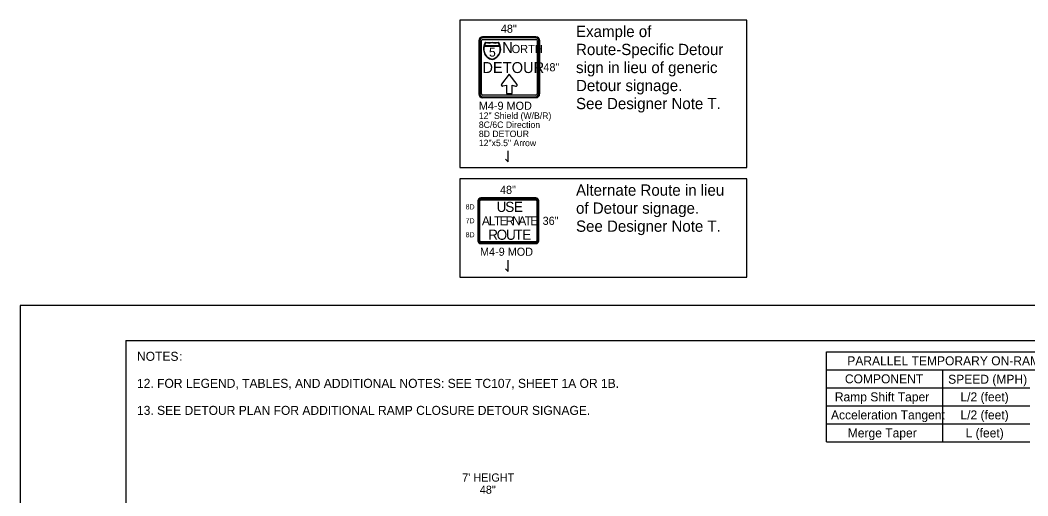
# Model space of a CAD drawing. Extents: x 99999 to 100116, y 99995 to 100013.
# Drawn here: x 100039.06 to 100048.01, y 100009 to 100013.22 of the extents above; entities that cross this region are included whole.
import ezdxf

# ---------------------------------------------------------------- set-up
doc = ezdxf.new("R2010")
doc.units = 0
for name, color, linetype in [('SH_GI_GeneralNotesBodyText', 7, 'Continuous'), ('SH_GI_PlotLimits', 7, 'Continuous'), ('SH_GI_SheetBorder', 7, 'Continuous'), ('SH_TI_Tables', 7, 'Continuous'), ('TR_SN_ConstructionSigns', 7, 'Continuous'), ('TR_WZ_WorkZoneDetails', 7, 'Continuous')]:
    doc.layers.add(name, color=color, linetype=linetype)

msp = doc.modelspace()

# ---------------------------------------------------------------- linework, layer by layer
at = {"layer": 'SH_GI_PlotLimits'}
msp.add_lwpolyline([(100039.0625, 99999.6875), (100056.0625, 99999.6875), (100056.0625, 100010.6875), (100039.0625, 100010.6875)], close=True, dxfattribs=at)
at = {"layer": 'SH_GI_SheetBorder'}
for q in [(100040, 100000), (100055.75, 100010.375)]:
    msp.add_line((100040, 100010.375), q, dxfattribs=at)
at = {"layer": 'SH_TI_Tables'}
for p, q in [((100046.2222, 100010.275), (100049.5278, 100010.275)), ((100046.2222, 100009.475), (100046.2222, 100010.275)), ((100046.2222, 100010.115), (100049.5278, 100010.115)), ((100047.2536, 100010.115), (100047.2536, 100009.795)), ((100046.2222, 100009.955), (100048.0278, 100009.955)), ((100046.2222, 100009.795), (100048.0278, 100009.795)), ((100047.2536, 100009.795), (100047.2536, 100009.635)), ((100046.2222, 100009.635), (100048.0278, 100009.635)), ((100047.2536, 100009.635), (100047.2536, 100009.475)), ((100046.2222, 100009.475), (100048.0278, 100009.475))]:
    msp.add_line(p, q, dxfattribs=at)
at = {"layer": 'TR_SN_ConstructionSigns'}
for p, q in [((100043.1354, 100013.0373), (100043.1354, 100012.5648)), ((100043.1438, 100013.0373), (100043.1438, 100012.5648)), ((100043.1579, 100012.5648), (100043.1579, 100013.0373)), ((100043.6416, 100013.0711), (100043.1691, 100013.0711)), ((100043.6416, 100013.0626), (100043.1691, 100013.0626)), ((100043.1691, 100013.0486), (100043.6416, 100013.0486)), ((100043.3228, 100012.9875), (100043.1823, 100012.9875)), ((100043.1823, 100012.9875), (100043.3228, 100012.9875)), ((100043.1834, 100012.9912), (100043.3217, 100012.9912)), ((100043.3217, 100012.9912), (100043.1834, 100012.9912)), ((100043.6529, 100013.0373), (100043.6529, 100012.5648)), ((100043.6669, 100012.5648), (100043.6669, 100013.0373)), ((100043.6754, 100012.5648), (100043.6754, 100013.0373)), ((100043.6416, 100012.5536), (100043.1691, 100012.5536)), ((100043.1691, 100012.5395), (100043.6416, 100012.5395)), ((100043.1691, 100012.5311), (100043.6416, 100012.5311)), ((100043.1277, 100011.6152), (100043.1277, 100011.2608)), ((100043.1347, 100011.6152), (100043.1347, 100011.2608)), ((100043.1446, 100011.2608), (100043.1446, 100011.6152)), ((100043.6424, 100011.6405), (100043.153, 100011.6405)), ((100043.6424, 100011.6335), (100043.153, 100011.6335)), ((100043.153, 100011.6236), (100043.6424, 100011.6236)), ((100043.6508, 100011.6152), (100043.6508, 100011.2608)), ((100043.6607, 100011.2608), (100043.6607, 100011.6152)), ((100043.6677, 100011.2608), (100043.6677, 100011.6152)), ((100043.6424, 100011.2524), (100043.153, 100011.2524)), ((100043.153, 100011.2425), (100043.6424, 100011.2425)), ((100043.153, 100011.2355), (100043.6424, 100011.2355))]:
    msp.add_line(p, q, dxfattribs=at)
msp.add_lwpolyline([(100043.3367, 100012.6494), (100043.3356, 100012.6478), (100043.335, 100012.6461), (100043.3347, 100012.6441), (100043.3348, 100012.6424), (100043.335, 100012.6412), (100043.3356, 100012.6398), (100043.3373, 100012.6375), (100043.3386, 100012.6364), (100043.34, 100012.6355), (100043.3417, 100012.6348), (100043.3432, 100012.6345), (100043.3447, 100012.6343), (100043.3465, 100012.6343), (100043.3478, 100012.6346), (100043.3795, 100012.6424), (100043.3795, 100012.5671), (100043.4307, 100012.5671), (100043.4307, 100012.6429), (100043.4617, 100012.6337), (100043.4647, 100012.6331), (100043.4681, 100012.6334), (100043.4703, 100012.6342), (100043.4733, 100012.6362), (100043.4752, 100012.6389), (100043.476, 100012.6414), (100043.4761, 100012.6436), (100043.4754, 100012.6463), (100043.4746, 100012.6477), (100043.4051, 100012.7405), (100043.3367, 100012.6494)], dxfattribs=at)
for centre, radius, start, end in [((100043.1691, 100013.0373), 0.0337, 90, 180), ((100043.1691, 100013.0373), 0.0253, 90, 180), ((100043.1691, 100013.0373), 0.0113, 90, 180), ((100043.2725, 100012.9642), 0.0973, 142.16169, 258.18105), ((100043.2715, 100012.9633), 0.0925, 164.85517, 258.18105), ((100043.2715, 100012.9633), 0.0925, 164.85517, 258.18105), ((100043.2715, 100012.9633), 0.0925, 142.16169, 162.48397), ((100043.2715, 100012.9633), 0.0925, 142.16169, 162.48397), ((100043.2245, 100013.1212), 0.1014, 253.48525, 286.04538), ((100043.2259, 100013.1124), 0.0964, 253.48525, 286.04538), ((100043.2259, 100013.1124), 0.0964, 253.48525, 286.04538), ((100043.2806, 100013.1212), 0.1014, 253.95462, 286.51475), ((100043.2792, 100013.1124), 0.0964, 253.95462, 286.51475), ((100043.2792, 100013.1124), 0.0964, 253.95462, 286.51475), ((100043.2325, 100012.9642), 0.0974, 281.90384, 37.84925), ((100043.2335, 100012.9633), 0.0925, 281.90384, 15.1558), ((100043.2335, 100012.9633), 0.0925, 281.90384, 15.1558), ((100043.2335, 100012.9633), 0.0925, 17.52691, 37.84925), ((100043.2335, 100012.9633), 0.0925, 17.52691, 37.84925), ((100043.6416, 100013.0373), 0.0338, 360, 90), ((100043.6416, 100013.0373), 0.0253, 360, 90), ((100043.6416, 100013.0373), 0.0113, 360, 90), ((100043.1691, 100012.5648), 0.0338, 180, 270), ((100043.1691, 100012.5648), 0.0253, 180, 270), ((100043.1691, 100012.5648), 0.0113, 180, 270), ((100043.6416, 100012.5648), 0.0337, 270, 360), ((100043.6416, 100012.5648), 0.0253, 270, 0), ((100043.6416, 100012.5648), 0.0113, 270, 0), ((100043.153, 100011.6152), 0.0253, 90, 180), ((100043.153, 100011.6152), 0.0183, 90, 180), ((100043.153, 100011.6152), 0.00844, 90, 180), ((100043.6424, 100011.6152), 0.0253, 360, 90), ((100043.6424, 100011.6152), 0.0183, 360, 90), ((100043.6424, 100011.6152), 0.00844, 360, 90), ((100043.153, 100011.2608), 0.0253, 180, 270), ((100043.153, 100011.2608), 0.0183, 180, 270), ((100043.153, 100011.2608), 0.00844, 180, 270), ((100043.6424, 100011.2608), 0.0253, 270, 360), ((100043.6424, 100011.2608), 0.0183, 270, 0), ((100043.6424, 100011.2608), 0.00844, 270, 0)]:
    msp.add_arc(centre, radius, start, end, dxfattribs=at)
at = {"layer": 'TR_WZ_WorkZoneDetails'}
for p, q in [((100043.3963, 100011.9605), (100043.3963, 100012.0605)), ((100043.3713, 100011.9855), (100043.3963, 100011.9605)), ((100043.3963, 100010.9875), (100043.3963, 100011.0875)), ((100043.3713, 100011.0125), (100043.3963, 100010.9875))]:
    msp.add_line(p, q, dxfattribs=at)
for points in [[(100042.9666, 100011.9105), (100045.5143, 100011.9105), (100045.5143, 100013.2191), (100042.9666, 100013.2191)], [(100042.9666, 100010.9375), (100045.5143, 100010.9375), (100045.5143, 100011.8105), (100042.9666, 100011.8105)]]:
    msp.add_lwpolyline(points, close=True, dxfattribs=at)

# ---------------------------------------------------------------- texts
at = {"layer": 'SH_GI_GeneralNotesBodyText'}
for s, p in [('NOTES', (100040.1, 100010.195)), (':', (100040.4743, 100010.195)), ('12. FOR LEGEND, TABLES, AND ADDITIONAL NOTES: SEE TC107, SHEET 1A OR 1B.', (100040.1, 100009.955)), ('13. SEE DETOUR PLAN FOR ADDITIONAL RAMP CLOSURE DETOUR SIGNAGE.', (100040.1, 100009.715))]:
    msp.add_text(s, height=0.08, rotation=360, dxfattribs=at).set_placement(p)
at = {"layer": 'SH_TI_Tables'}
for s, p in [('PARALLEL TEMPORARY ON-RAMP MERGE (1-LANE)', (100046.4067, 100010.155)), ('COMPONENT', (100046.3855, 100009.995)), ('SPEED (MPH)', (100047.3025, 100009.9915)), ('Ramp Shift Taper', (100046.2963, 100009.835)), ('L/2 (feet)', (100047.4117, 100009.835)), ('Acceleration Tangent', (100046.2622, 100009.675)), ('L/2 (feet)', (100047.4117, 100009.675)), ('Merge Taper', (100046.411, 100009.515)), ('L (feet)', (100047.457, 100009.515))]:
    msp.add_text(s, height=0.08, rotation=360, dxfattribs=at).set_placement(p)
at = {"layer": 'TR_SN_ConstructionSigns'}
for s, height, p in [('48"', 0.072, (100043.3306, 100013.1071)), ('N', 0.0972, (100043.3432, 100012.9267)), ('ORTH', 0.0729, (100043.4264, 100012.9267)), ('5', 0.081, (100043.2253, 100012.8951)), ('DETOUR', 0.0972, (100043.1668, 100012.7497)), ('48"', 0.072, (100043.7086, 100012.7651)), ('M4-9 MOD', 0.072, (100043.1354, 100012.4231)), ('12" Shield (W/B/R)', 0.0576, (100043.1354, 100012.3424)), ('8C/6C Direction', 0.0576, (100043.1354, 100012.2618)), ('8D DETOUR', 0.0576, (100043.1354, 100012.1811)), ('12"x5.5" Arrow', 0.0576, (100043.1354, 100012.1005)), ('48"', 0.072, (100043.323, 100011.6765)), ('36"', 0.072, (100043.7015, 100011.402)), ('M4-9 MOD', 0.072, (100043.1457, 100011.1275)), ("7' HEIGHT", 0.072, (100042.9875, 100009.1229)), ('48"', 0.072, (100043.144, 100009.0149))]:
    msp.add_text(s, height=height, rotation=360, dxfattribs=at).set_placement(p)
for s, height, p in [('8D', 0.045, (100043.018, 100011.5392)), ('U', 0.09, (100043.2933, 100011.5167)), ('S', 0.09, (100043.3698, 100011.5167)), ('E', 0.09, (100043.4463, 100011.5167)), ('A', 0.0787, (100043.1626, 100011.3986)), ('L', 0.0787, (100043.2241, 100011.3986)), ('T', 0.0787, (100043.269, 100011.3986)), ('E', 0.0787, (100043.3201, 100011.3986)), ('R', 0.0787, (100043.3737, 100011.3986)), ('N', 0.0787, (100043.4312, 100011.3986)), ('A', 0.0787, (100043.4863, 100011.3986)), ('T', 0.0787, (100043.5414, 100011.3986)), ('E', 0.0787, (100043.5926, 100011.3986)), ('7D', 0.045, (100043.018, 100011.4155)), ('8D', 0.045, (100043.018, 100011.2917)), ('R', 0.09, (100043.2186, 100011.2692)), ('O', 0.09, (100043.2933, 100011.2692)), ('U', 0.09, (100043.377, 100011.2692)), ('T', 0.09, (100043.4517, 100011.2692)), ('E', 0.09, (100043.521, 100011.2692))]:
    msp.add_text(s, height=height, dxfattribs=at).set_placement(p)
at = {"layer": 'TR_WZ_WorkZoneDetails'}
for s, p in [('Example of ', (100043.9983, 100013.0691)), ('Route-Specific Detour ', (100043.9983, 100012.9091)), ('sign in lieu of generic ', (100043.9983, 100012.7491)), ('Detour signage.', (100043.9983, 100012.5891)), ('See Designer Note T.', (100043.9983, 100012.4291)), ('Alternate Route in lieu ', (100043.9983, 100011.6605)), ('of Detour signage.', (100043.9983, 100011.5005)), ('See Designer Note T.', (100043.9983, 100011.3405))]:
    msp.add_text(s, height=0.1, dxfattribs=at).set_placement(p)

doc.saveas('drawing.dxf')
